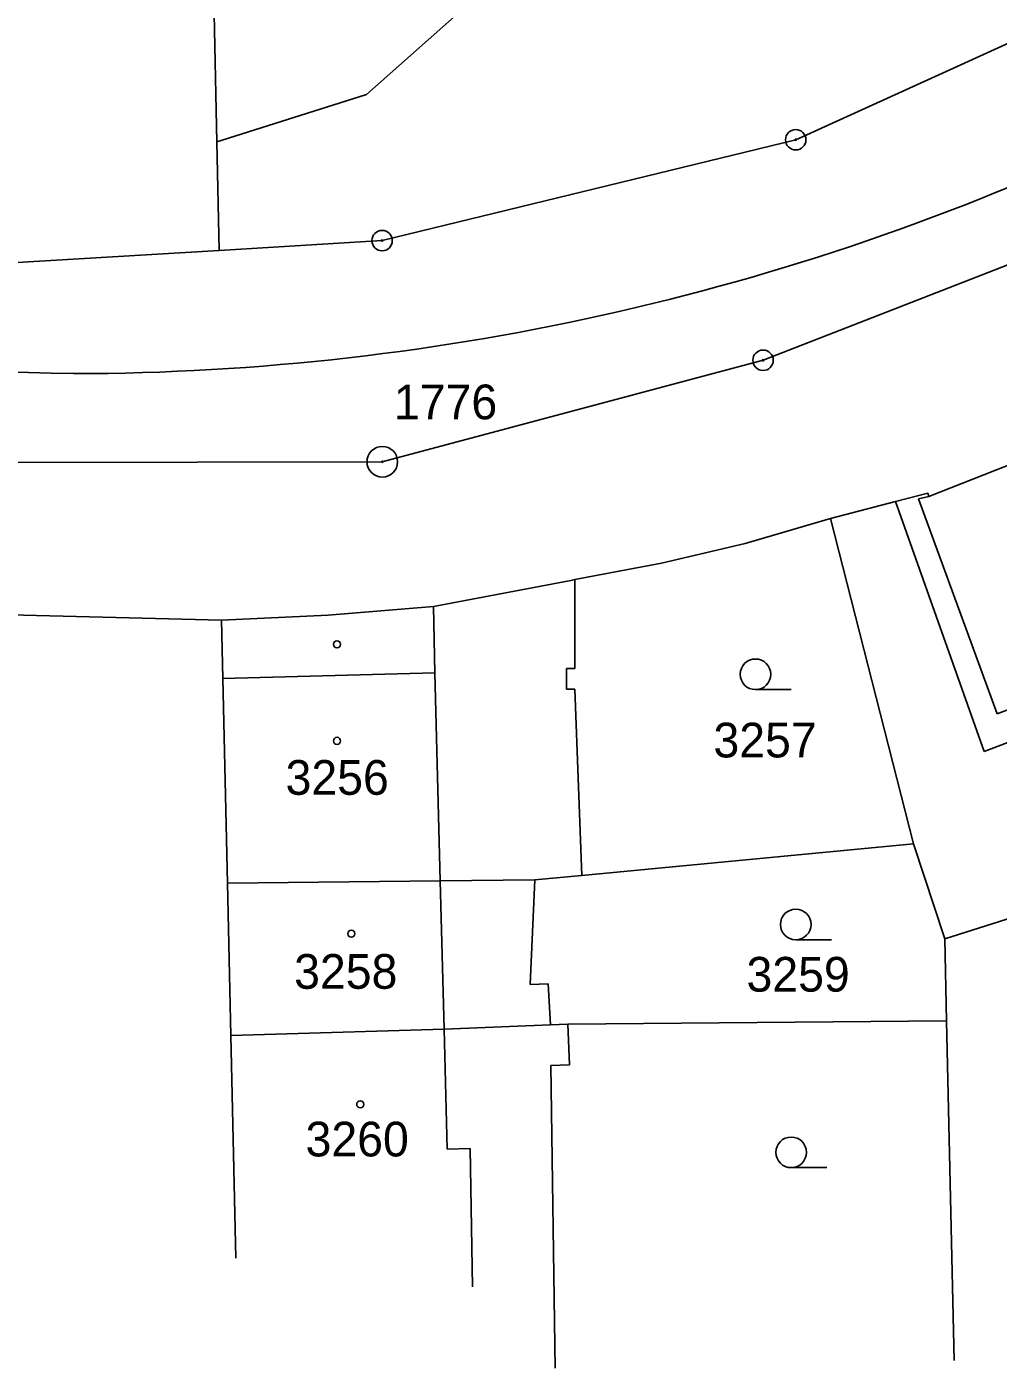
# Model space of a CAD drawing. Extents: x -735092 to -733385, y -1122435 to -1118992.
# Drawn here: x -734579.8 to -734532.2, y -1120273.9 to -1120208.2 of the extents above; entities that cross this region are included whole.
import ezdxf

# ---------------------------------------------------------------- set-up
doc = ezdxf.new("R2010")
doc.units = 0
for name, color, linetype in [('Vrstva 1', 7, 'Continuous'), ('Vrstva 10', 7, 'Continuous'), ('Vrstva 17', 7, 'Continuous'), ('Vrstva 18', 7, 'Continuous'), ('Vrstva 19', 7, 'Continuous'), ('Vrstva 25', 7, 'Continuous'), ('Vrstva 4', 7, 'Continuous')]:
    doc.layers.add(name, color=color, linetype=linetype)

msp = doc.modelspace()

# ---------------------------------------------------------------- linework, layer by layer
at = {"layer": 'Vrstva 1'}
for points in [[(-734570.82, -1120196.6), (-734570.46, -1120213.84)], [(-734542.11, -1120213.74), (-734525.37, -1120206.12)], [(-734563.13, -1120211.53), (-734558.68, -1120207.57)], [(-734570.21, -1120213.76), (-734563.13, -1120211.53)], [(-734570.46, -1120213.84), (-734570.21, -1120213.76)], [(-734570.46, -1120213.84), (-734570.35, -1120219.16)], [(-734562.37, -1120218.68), (-734542.11, -1120213.74)], [(-734543.71, -1120224.54), (-734522.92, -1120216.44)], [(-734570.35, -1120219.16), (-734562.37, -1120218.68)], [(-734585.49, -1120220.06), (-734570.35, -1120219.16)], [(-734562.36, -1120229.51), (-734543.71, -1120224.54)], [(-734535.59, -1120231.21), (-734528.66, -1120228.48)], [(-734589.59, -1120229.56), (-734562.36, -1120229.51)], [(-734537.22, -1120231.46), (-734535.63, -1120231.04)], [(-734535.63, -1120231.04), (-734535.59, -1120231.21)], [(-734540.41, -1120232.29), (-734537.22, -1120231.46)], [(-734537.22, -1120231.46), (-734532.88, -1120243.7)], [(-734544.58, -1120233.52), (-734540.41, -1120232.29)], [(-734540.41, -1120232.29), (-734536.34, -1120248.22)], [(-734548.69, -1120234.47), (-734544.58, -1120233.52)], [(-734552.93, -1120235.28), (-734548.69, -1120234.47)], [(-734559.86, -1120236.6), (-734553.13, -1120235.32)], [(-734553.13, -1120235.32), (-734552.93, -1120235.28)], [(-734552.93, -1120239.63), (-734552.93, -1120235.28)], [(-734581.9, -1120236.98), (-734570.24, -1120237.27)], [(-734570.24, -1120237.27), (-734565.01, -1120237.03)], [(-734565.01, -1120237.03), (-734559.86, -1120236.6)], [(-734570.24, -1120237.27), (-734570.18, -1120240.13)], [(-734553.34, -1120239.63), (-734552.93, -1120239.63)], [(-734553.34, -1120239.63), (-734553.34, -1120240.64)], [(-734570.18, -1120240.13), (-734569.95, -1120250.14)], [(-734532.88, -1120243.7), (-734524.13, -1120240.37)], [(-734553.34, -1120240.64), (-734552.93, -1120240.64)], [(-734552.93, -1120240.64), (-734552.58, -1120249.77)], [(-734552.58, -1120249.77), (-734536.34, -1120248.22)], [(-734536.34, -1120248.22), (-734534.81, -1120252.87)], [(-734534.81, -1120252.87), (-734523.37, -1120249.25)], [(-734569.95, -1120250.14), (-734559.52, -1120250.03)], [(-734569.95, -1120250.14), (-734569.78, -1120257.61)], [(-734559.52, -1120250.03), (-734554.89, -1120249.99)], [(-734555.12, -1120255.11), (-734554.89, -1120249.99)], [(-734554.89, -1120249.99), (-734552.58, -1120249.77)], [(-734534.81, -1120252.87), (-734534.72, -1120256.89)], [(-734555.12, -1120255.11), (-734554.24, -1120255.08)], [(-734554.24, -1120255.08), (-734554.12, -1120257.09)], [(-734553.27, -1120257.06), (-734534.72, -1120256.89)], [(-734534.72, -1120256.89), (-734534.35, -1120273.53)], [(-734569.78, -1120257.61), (-734559.33, -1120257.29)], [(-734559.33, -1120257.29), (-734554.12, -1120257.09)], [(-734554.12, -1120257.09), (-734553.27, -1120257.06)], [(-734553.27, -1120257.06), (-734553.19, -1120259.04)], [(-734569.78, -1120257.61), (-734569.54, -1120268.51)], [(-734554.11, -1120259.07), (-734553.19, -1120259.04)], [(-734554.11, -1120259.07), (-734553.9, -1120273.9)]]:
    msp.add_lwpolyline(points, dxfattribs=at)
at = {"layer": 'Vrstva 10'}
for centre, radius, start, end in [((-734577.688, -1120104.718), 120.479, 270.49893, 296.13651), ((-734575.637, -1120044.438), 180.753, 258.59022, 269.76346)]:
    msp.add_arc(centre, radius, start, end, dxfattribs=at)
at = {"layer": 'Vrstva 25'}
for points in [[(-734544.08, -1120240.67), (-734542.33, -1120240.67)], [(-734542.11, -1120252.92), (-734540.36, -1120252.92)], [(-734542.33, -1120264.08), (-734540.58, -1120264.08)]]:
    msp.add_lwpolyline(points, dxfattribs=at)
for centre, radius in [((-734542.11, -1120213.74), 0.5), ((-734542.11, -1120213.74), 0.032), ((-734562.37, -1120218.68), 0.5), ((-734562.37, -1120218.68), 0.032), ((-734543.71, -1120224.54), 0.5), ((-734543.71, -1120224.54), 0.032), ((-734562.36, -1120229.51), 0.75), ((-734562.36, -1120229.51), 0.032), ((-734564.58, -1120238.45), 0.175), ((-734544.08, -1120239.92), 0.75), ((-734564.58, -1120243.18), 0.175), ((-734542.11, -1120252.17), 0.75), ((-734563.88, -1120252.62), 0.175), ((-734563.44, -1120260.98), 0.175), ((-734542.33, -1120263.33), 0.75)]:
    msp.add_circle(centre, radius, dxfattribs=at)
at = {"layer": 'Vrstva 4'}
for points in [[(-734536.09, -1120231.32), (-734535.59, -1120231.21)], [(-734536.09, -1120231.32), (-734532.24, -1120241.86)], [(-734559.86, -1120236.6), (-734559.78, -1120239.85)], [(-734532.24, -1120241.86), (-734524.66, -1120238.96)], [(-734570.18, -1120240.13), (-734559.78, -1120239.85)], [(-734559.78, -1120239.85), (-734559.52, -1120250.03)], [(-734559.52, -1120250.03), (-734559.33, -1120257.29)], [(-734559.33, -1120257.29), (-734559.18, -1120263.17)], [(-734559.18, -1120263.17), (-734558.05, -1120263.15)], [(-734558.05, -1120263.15), (-734557.94, -1120269.92)]]:
    msp.add_lwpolyline(points, dxfattribs=at)

# ---------------------------------------------------------------- texts
at = {"layer": 'Vrstva 17'}
msp.add_text('1776', height=1.7, dxfattribs=at).set_placement((-734561.79, -1120227.43))
at = {"layer": 'Vrstva 18'}
for s, p in [('3257', (-734546.14, -1120243.99)), ('3259', (-734544.52, -1120255.46))]:
    msp.add_text(s, height=1.7, dxfattribs=at).set_placement(p)
at = {"layer": 'Vrstva 19'}
for s, p in [('3256', (-734567.1, -1120245.82)), ('3258', (-734566.68, -1120255.32)), ('3260', (-734566.12, -1120263.53))]:
    msp.add_text(s, height=1.7, dxfattribs=at).set_placement(p)

doc.saveas('drawing.dxf')
